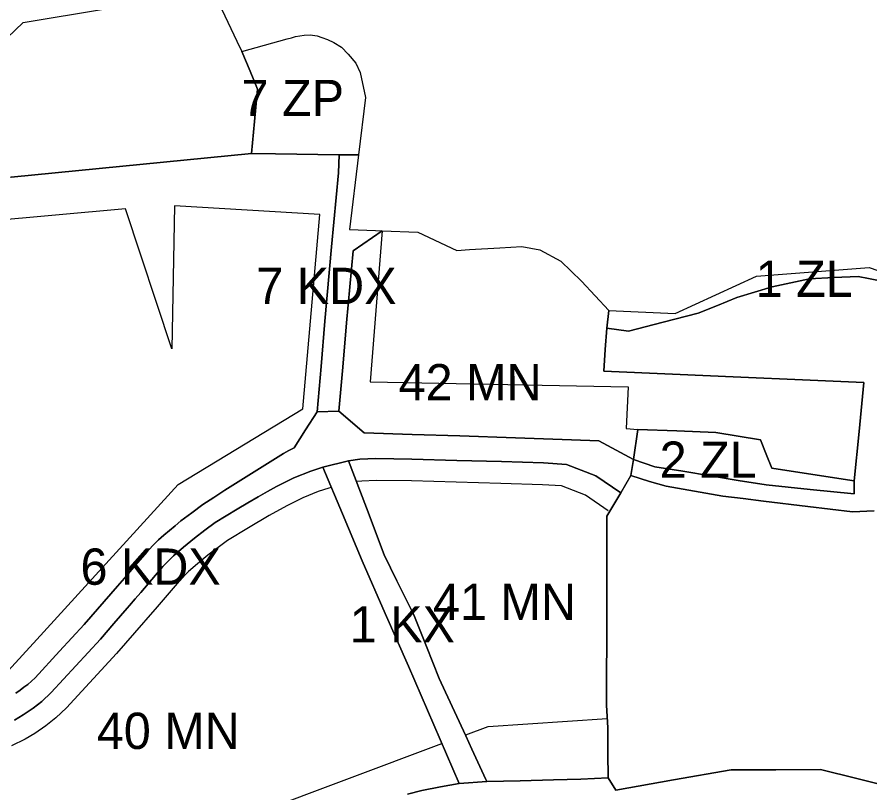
# Model space of a CAD drawing. Extents: x 7423432 to 7425824, y 5537848 to 5539677.
# Drawn here: x 7424420.7 to 7424655.7, y 5539274.6 to 5539488.4 of the extents above; entities that cross this region are included whole.
import ezdxf

# ---------------------------------------------------------------- set-up
doc = ezdxf.new("R2010")
doc.units = 0
for name, color, linetype in [('linie_rozgraniczajace', 7, 'Continuous'), ('linie_zabudowy_nieprzekraczalne', 7, 'Continuous'), ('oznaczenia_przeznaczen', 7, 'Continuous')]:
    doc.layers.add(name, color=color, linetype=linetype)

msp = doc.modelspace()

# ---------------------------------------------------------------- linework, layer by layer
at = {"layer": 'linie_rozgraniczajace'}
for points in [[(7424477.08, 5539490.55), (7424481.18, 5539481.82), (7424482.56, 5539478.9), (7424484.89, 5539473.48), (7424486.96, 5539468.52), (7424486.12, 5539459.68), (7424485.29, 5539450.85), (7424419.02, 5539444.34), (7424352.75, 5539437.84), (7424319.32, 5539435.23), (7424285.89, 5539432.62)], [(7424396.14, 5539489.1), (7424398.27, 5539483.53), (7424401.86, 5539484.56), (7424403.06, 5539482.79), (7424412.69, 5539483.41), (7424417.64, 5539482.77), (7424417.94, 5539482.73), (7424422.37, 5539486.9), (7424445.03, 5539490.67)], [(7424419.02, 5539444.34), (7424485.29, 5539450.85), (7424491.9, 5539450.74), (7424509.45, 5539450.49), (7424509.2, 5539445.52), (7424507.35, 5539425.09), (7424505.5, 5539404.65), (7424504.42, 5539392.13), (7424503.35, 5539379.6), (7424500.18, 5539374.67), (7424497.01, 5539369.73), (7424495.55, 5539368.95), (7424494.1, 5539368.17), (7424486, 5539363.11), (7424477.9, 5539358.05), (7424474.87, 5539356.04), (7424471.85, 5539354.03), (7424468.83, 5539351.78), (7424465.82, 5539349.53), (7424464.23, 5539348.23), (7424462.64, 5539346.93), (7424461.13, 5539345.62), (7424459.62, 5539344.32), (7424458.01, 5539342.64), (7424456.41, 5539340.97), (7424453.33, 5539337.35), (7424450.24, 5539333.73), (7424448.35, 5539331.59), (7424442.8, 5539325.21), (7424439.14, 5539320.98), (7424432.38, 5539313.63), (7424425.62, 5539306.27), (7424424.63, 5539305.39), (7424423.63, 5539304.5), (7424422.57, 5539303.68), (7424421.51, 5539302.86), (7424420.32, 5539302.05)], [(7424658.03, 5539415.82), (7424655.31, 5539416.37), (7424652.47, 5539416.96), (7424645.74, 5539416.64), (7424639.01, 5539416.31), (7424633.89, 5539415.2), (7424628.78, 5539414.09), (7424623.88, 5539412.6), (7424618.97, 5539411.12), (7424613.66, 5539408.97), (7424608.34, 5539406.81), (7424598.75, 5539404.33), (7424589.16, 5539401.84), (7424583.19, 5539402.67), (7424583.7, 5539407.57), (7424601.98, 5539406.76), (7424624.44, 5539416.97), (7424655.45, 5539419.36), (7424683.01, 5539409.88)], [(7424582.36, 5539390.87), (7424582.77, 5539396.77), (7424583.19, 5539402.67), (7424589.16, 5539401.84), (7424598.75, 5539404.33), (7424608.34, 5539406.81), (7424613.66, 5539408.97), (7424618.97, 5539411.12), (7424623.88, 5539412.6), (7424628.78, 5539414.09), (7424633.89, 5539415.2), (7424639.01, 5539416.31), (7424645.74, 5539416.64), (7424652.47, 5539416.96), (7424655.31, 5539416.37), (7424658.03, 5539415.82)], [(7424590.5, 5539366.46), (7424596.45, 5539364.5), (7424604.1, 5539363.24), (7424611.76, 5539361.98), (7424619.42, 5539360.72), (7424627.08, 5539359.46), (7424639.24, 5539358.22), (7424651.39, 5539356.99), (7424651.39, 5539358.75), (7424651.39, 5539360.57), (7424652.7, 5539374.15), (7424654.02, 5539387.72), (7424637.09, 5539388.45), (7424620.16, 5539389.17), (7424601.26, 5539390.02), (7424582.36, 5539390.87)], [(7424420.32, 5539302.05), (7424421.51, 5539302.86), (7424422.57, 5539303.68), (7424423.63, 5539304.5), (7424424.63, 5539305.39), (7424425.62, 5539306.27), (7424432.38, 5539313.63), (7424439.14, 5539320.98), (7424442.8, 5539325.21), (7424448.35, 5539331.59), (7424450.24, 5539333.73), (7424453.33, 5539337.35), (7424456.41, 5539340.97), (7424458.01, 5539342.64), (7424459.62, 5539344.32), (7424461.13, 5539345.62), (7424462.64, 5539346.93), (7424464.23, 5539348.23), (7424465.82, 5539349.53), (7424468.83, 5539351.78), (7424471.85, 5539354.03), (7424474.87, 5539356.04), (7424477.9, 5539358.05), (7424486, 5539363.11), (7424494.1, 5539368.17), (7424495.55, 5539368.95), (7424497.01, 5539369.73), (7424500.18, 5539374.67), (7424503.35, 5539379.6), (7424509.36, 5539379.82), (7424516.3, 5539373.8), (7424529.51, 5539373.4), (7424542.71, 5539373), (7424558.06, 5539372.43), (7424573.41, 5539371.87), (7424580.98, 5539371.6), (7424590.5, 5539366.46), (7424589.83, 5539362.04), (7424587.01, 5539357.26), (7424580.14, 5539362.02), (7424576.09, 5539363.56), (7424572.04, 5539365.1), (7424565.78, 5539365.54), (7424559.98, 5539365.72), (7424554.18, 5539365.89), (7424541.82, 5539366.24), (7424529.47, 5539366.59), (7424524.48, 5539366.66), (7424519.5, 5539366.72), (7424517.33, 5539366.63), (7424515.15, 5539366.54), (7424512, 5539366.15), (7424504.96, 5539364.33), (7424501.6, 5539363.27), (7424496.93, 5539361.39), (7424492.19, 5539359.02), (7424489.67, 5539357.62), (7424487.14, 5539356.21), (7424484.23, 5539354.49), (7424481.32, 5539352.78), (7424478.31, 5539350.95), (7424475.3, 5539349.13), (7424472.41, 5539346.96), (7424469.52, 5539344.8), (7424466.5, 5539342.33), (7424463.75, 5539339.96), (7424462.31, 5539338.45), (7424460.87, 5539336.95), (7424457.82, 5539333.37), (7424454.77, 5539329.8), (7424453.21, 5539328.04), (7424451.65, 5539326.27), (7424450.99, 5539325.51), (7424447.3, 5539321.25), (7424443.62, 5539316.99), (7424436.83, 5539309.6), (7424430.04, 5539302.21), (7424427.47, 5539299.8), (7424426.28, 5539298.87), (7424425.08, 5539297.93), (7424423.7, 5539297), (7424422.32, 5539296.07), (7424421.14, 5539295.37), (7424419.96, 5539294.67)], [(7424656.88, 5539352.33), (7424650.88, 5539352.03), (7424638.61, 5539353.52), (7424626.34, 5539355.01), (7424620.76, 5539355.71), (7424615.17, 5539356.4), (7424607.37, 5539357.77), (7424599.56, 5539359.13), (7424594.94, 5539360.4), (7424592.38, 5539361.22), (7424589.83, 5539362.04), (7424590.5, 5539366.46)], [(7424419.96, 5539294.67), (7424421.14, 5539295.37), (7424422.32, 5539296.07), (7424423.7, 5539297), (7424425.08, 5539297.93), (7424426.28, 5539298.87), (7424427.47, 5539299.8), (7424430.04, 5539302.21), (7424436.83, 5539309.6), (7424443.62, 5539316.99), (7424447.3, 5539321.25), (7424450.99, 5539325.51), (7424451.65, 5539326.27), (7424453.21, 5539328.04), (7424454.77, 5539329.8), (7424457.82, 5539333.37), (7424460.87, 5539336.95), (7424462.31, 5539338.45), (7424463.75, 5539339.96), (7424466.5, 5539342.33), (7424469.52, 5539344.8), (7424472.41, 5539346.96), (7424475.3, 5539349.13), (7424478.31, 5539350.95), (7424481.32, 5539352.78), (7424484.23, 5539354.49), (7424487.14, 5539356.21), (7424489.67, 5539357.62), (7424492.19, 5539359.02), (7424496.93, 5539361.39), (7424501.6, 5539363.27), (7424504.96, 5539364.33), (7424510.36, 5539351.46), (7424515.75, 5539338.59), (7424522.12, 5539324.04), (7424528.49, 5539309.5), (7424535.47, 5539293.34), (7424542.45, 5539277.17), (7424537.33, 5539276.22), (7424532.21, 5539275.26), (7424528.28, 5539274.19)], [(7424583.52, 5539278.69), (7424583.5, 5539285.59), (7424583.49, 5539292.5), (7424583.08, 5539298.79), (7424583.15, 5539324.8), (7424583.22, 5539350.82), (7424587.01, 5539357.26), (7424589.83, 5539362.04), (7424592.38, 5539361.22), (7424594.94, 5539360.4), (7424599.56, 5539359.13), (7424607.37, 5539357.77), (7424615.17, 5539356.4), (7424620.76, 5539355.71), (7424626.34, 5539355.01), (7424638.61, 5539353.52), (7424650.88, 5539352.03), (7424656.88, 5539352.33)], [(7424528.28, 5539274.19), (7424532.21, 5539275.26), (7424537.33, 5539276.22), (7424542.45, 5539277.17), (7424550.13, 5539277.76), (7424559.32, 5539277.95), (7424568.52, 5539278.14), (7424576.02, 5539278.41), (7424583.52, 5539278.69), (7424585.65, 5539275.31), (7424601.53, 5539278.14), (7424617.42, 5539280.98), (7424629.76, 5539280.98), (7424642.11, 5539280.99), (7424652.04, 5539278.53), (7424661.96, 5539276.08)], [(7424617.42, 5539280.98), (7424601.53, 5539278.14), (7424585.65, 5539275.31), (7424583.52, 5539278.69)], [(7424661.96, 5539276.08), (7424652.04, 5539278.53), (7424642.11, 5539280.99), (7424629.76, 5539280.98), (7424617.42, 5539280.98)]]:
    msp.add_lwpolyline(points, dxfattribs=at)
for points in [[(7424482.56, 5539478.9), (7424495.09, 5539482.39), (7424496.26, 5539482.72), (7424497.42, 5539483.09), (7424499.79, 5539483.43), (7424501.48, 5539483.56), (7424503.32, 5539483.23), (7424504.65, 5539482.78), (7424506.22, 5539482.24), (7424507.93, 5539481.44), (7424510.03, 5539480.09), (7424511.89, 5539478.2), (7424513.98, 5539475.69), (7424515.21, 5539473.16), (7424516.64, 5539466.29), (7424514.72, 5539450.42), (7424509.45, 5539450.49), (7424491.9, 5539450.74), (7424485.29, 5539450.85), (7424486.12, 5539459.68), (7424486.96, 5539468.52), (7424484.89, 5539473.48)], [(7424503.35, 5539379.6), (7424504.42, 5539392.13), (7424505.5, 5539404.65), (7424507.35, 5539425.09), (7424509.2, 5539445.52), (7424509.45, 5539450.49), (7424514.72, 5539450.42), (7424512.24, 5539429.88), (7424519.44, 5539429.57), (7424521.32, 5539429.46), (7424513.26, 5539423.99), (7424512.37, 5539414.05), (7424511.47, 5539404.12), (7424510.41, 5539391.97), (7424509.36, 5539379.82)], [(7424509.36, 5539379.82), (7424510.41, 5539391.97), (7424511.47, 5539404.12), (7424512.37, 5539414.05), (7424513.26, 5539423.99), (7424521.32, 5539429.46), (7424531.14, 5539429.15), (7424541.82, 5539424.11), (7424545.31, 5539424.32), (7424553.69, 5539424.83), (7424559.74, 5539425.17), (7424564.73, 5539424.29), (7424570.52, 5539421.19), (7424576.18, 5539415.65), (7424583.7, 5539407.57), (7424583.19, 5539402.67), (7424582.77, 5539396.77), (7424582.36, 5539390.87), (7424601.26, 5539390.02), (7424620.16, 5539389.17), (7424637.09, 5539388.45), (7424654.02, 5539387.72), (7424652.7, 5539374.15), (7424651.39, 5539360.57), (7424640, 5539362.32), (7424628.62, 5539364.07), (7424627.07, 5539367.98), (7424625.52, 5539371.88), (7424619.36, 5539372.91), (7424613.21, 5539373.95), (7424602.48, 5539374.35), (7424591.76, 5539374.76), (7424590.5, 5539366.46), (7424580.98, 5539371.6), (7424573.41, 5539371.87), (7424558.06, 5539372.43), (7424542.71, 5539373), (7424529.51, 5539373.4), (7424516.3, 5539373.8)], [(7424590.5, 5539366.46), (7424591.76, 5539374.76), (7424602.48, 5539374.35), (7424613.21, 5539373.95), (7424619.36, 5539372.91), (7424625.52, 5539371.88), (7424627.07, 5539367.98), (7424628.62, 5539364.07), (7424640, 5539362.32), (7424651.39, 5539360.57), (7424651.39, 5539358.75), (7424651.39, 5539356.99), (7424639.24, 5539358.22), (7424627.08, 5539359.46), (7424619.42, 5539360.72), (7424611.76, 5539361.98), (7424604.1, 5539363.24), (7424596.45, 5539364.5)], [(7424504.96, 5539364.33), (7424512, 5539366.15), (7424516.92, 5539353.18), (7424521.84, 5539340.21), (7424525.35, 5539333.08), (7424529.96, 5539323.7), (7424533.45, 5539314.91), (7424536.95, 5539306.11), (7424538.72, 5539302.33), (7424544.3, 5539290.33), (7424545.99, 5539286.68), (7424549.88, 5539278.32), (7424550.13, 5539277.76), (7424542.45, 5539277.17), (7424535.47, 5539293.34), (7424528.49, 5539309.5), (7424522.12, 5539324.04), (7424515.75, 5539338.59), (7424510.36, 5539351.46)], [(7424512, 5539366.15), (7424515.15, 5539366.54), (7424517.33, 5539366.63), (7424519.5, 5539366.72), (7424524.48, 5539366.66), (7424529.47, 5539366.59), (7424541.82, 5539366.24), (7424554.18, 5539365.89), (7424559.98, 5539365.72), (7424565.78, 5539365.54), (7424572.04, 5539365.1), (7424576.09, 5539363.56), (7424580.14, 5539362.02), (7424587.01, 5539357.26), (7424583.22, 5539350.82), (7424583.15, 5539324.8), (7424583.08, 5539298.79), (7424583.49, 5539292.5), (7424583.5, 5539285.59), (7424583.52, 5539278.69), (7424576.02, 5539278.41), (7424568.52, 5539278.14), (7424559.32, 5539277.95), (7424550.13, 5539277.76), (7424549.88, 5539278.32), (7424545.99, 5539286.68), (7424544.3, 5539290.33), (7424538.72, 5539302.33), (7424536.95, 5539306.11), (7424533.45, 5539314.91), (7424529.96, 5539323.7), (7424525.35, 5539333.08), (7424521.84, 5539340.21), (7424516.92, 5539353.18)]]:
    msp.add_lwpolyline(points, close=True, dxfattribs=at)
at = {"layer": 'linie_zabudowy_nieprzekraczalne'}
for points in [[(7424464.09, 5539436.39), (7424463.29, 5539396.95), (7424450.52, 5539435.6), (7424298.13, 5539421.81), (7424293.96, 5539421.24), (7424303.75, 5539351.91), (7424315.76, 5539269.24), (7424326.17, 5539216.7), (7424391.29, 5539228.61), (7424389.98, 5539236.5), (7424379.98, 5539254.3), (7424375.1, 5539252.12), (7424354.77, 5539295.74), (7424393.75, 5539306.92), (7424396.74, 5539298.44), (7424418.21, 5539308.25), (7424426.15, 5539316.84), (7424465.06, 5539359.62), (7424499.41, 5539380.44), (7424504.14, 5539433.99), (7424464.09, 5539436.39)], [(7424521.32, 5539429.46), (7424517.93, 5539387.91), (7424589.11, 5539386.49), (7424588.49, 5539375.05), (7424591.76, 5539374.76)], [(7424583.6, 5539352.33), (7424577.32, 5539356.68), (7424570.74, 5539359.18), (7424565.48, 5539359.54), (7424554, 5539359.9), (7424529.35, 5539360.59), (7424519.59, 5539360.72), (7424515.65, 5539360.55), (7424514.19, 5539360.37)], [(7424507.3, 5539358.74), (7424506.61, 5539358.56), (7424503.62, 5539357.62), (7424499.4, 5539355.92), (7424495, 5539353.72), (7424490.12, 5539351), (7424484.4, 5539347.63), (7424478.66, 5539344.15), (7424473.21, 5539340.07), (7424470.36, 5539337.74), (7424467.89, 5539335.61), (7424465.32, 5539332.92), (7424459.31, 5539325.87), (7424456.16, 5539322.31), (7424455.52, 5539321.58), (7424448.09, 5539312.99), (7424434.31, 5539297.99), (7424431.38, 5539295.25), (7424428.61, 5539293.07), (7424425.52, 5539291), (7424422.86, 5539289.42), (7424419.17, 5539287.52)], [(7424544.33, 5539290.58), (7424550.49, 5539292.91), (7424583.32, 5539295.11)], [(7424409.7, 5539240.15), (7424537.69, 5539288.2)]]:
    msp.add_lwpolyline(points, dxfattribs=at)

# ---------------------------------------------------------------- texts
at = {"layer": 'oznaczenia_przeznaczen'}
for s, p in [('7 ZP', (7424482.53, 5539461.12)), ('1 ZL', (7424624.2, 5539411.31)), ('7 KDX', (7424486.59, 5539409.33)), ('42 MN', (7424525.81, 5539382.78)), ('2 ZL', (7424597.75, 5539361.43)), ('6 KDX', (7424438.14, 5539331.95)), ('41 MN', (7424535.28, 5539322.24)), ('1 KX', (7424512.35, 5539316.04)), ('40 MN', (7424442.64, 5539286.69))]:
    msp.add_text(s, height=10, dxfattribs=at).set_placement(p)

doc.saveas('drawing.dxf')
